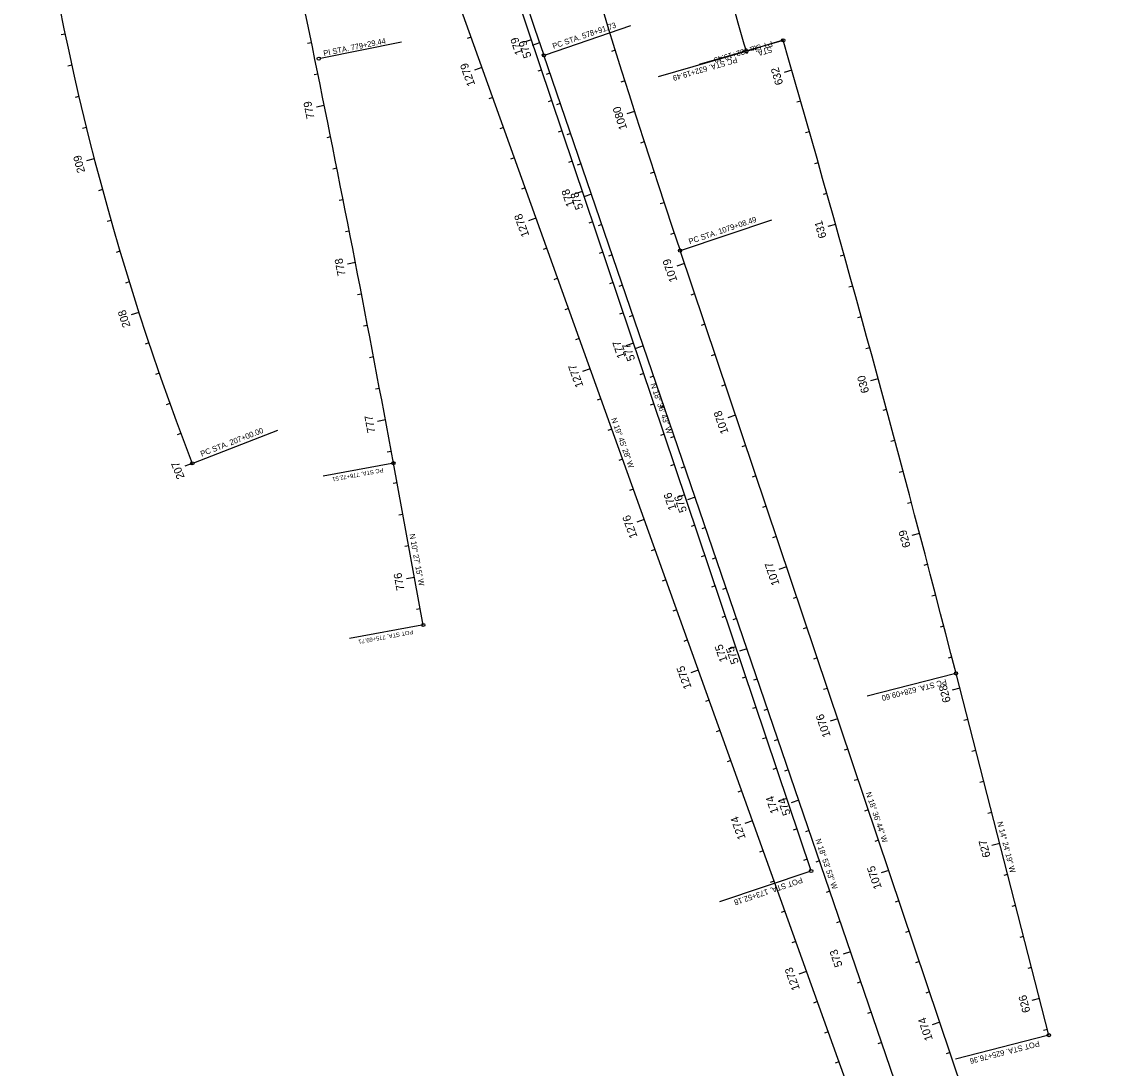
# Model space of a CAD drawing. Extents: x 919452 to 931278, y 583254 to 665650.
# Drawn here: x 928968 to 929643, y 633142 to 633795 of the extents above; entities that cross this region are included whole.
import ezdxf

# ---------------------------------------------------------------- set-up
doc = ezdxf.new("R2010")
doc.units = 0
for name, color, linetype in [('CLConst_dp', 7, 'Continuous'), ('CurveDataLabel_dp', 7, 'Continuous'), ('StationTicL_dp', 7, 'Continuous'), ('StationTicS_dp', 7, 'Continuous'), ('TextBLStation', 7, 'Continuous'), ('TextLabel', 7, 'Continuous')]:
    doc.layers.add(name, color=color, linetype=linetype)

msp = doc.modelspace()

# ---------------------------------------------------------------- linework, layer by layer
at = {"layer": 'CLConst_dp'}
for p, q in [((929494.71, 633100.38), (929187.7, 633955.08)), ((929461.08, 633264.99), (929269.59, 633833.59)), ((929443.57, 633783.76), (929420.55, 633776.95)), ((929642.97, 632755.12), (929294.03, 633774.41)), ((929620.57, 632935.53), (929379.13, 633652.46)), ((929218.69, 633418.59), (929200.03, 633519.68)), ((929609.57, 633162.46), (929551.54, 633388.36))]:
    msp.add_line(p, q, dxfattribs=at)
for centre, radius, start, end in [((934714.76, 635630.15), 5729.58, 175.955434, 198.89818), ((934799.58, 635477.92), 5719.58, 193.88471, 198.61214), ((915974, 631079.31), 13449.29, 10.454203, 12.643022), ((930687.21, 634143.64), 1729.38, 186.13885, 201.15388), ((916462.13, 630026.27), 13490.3, 16.142538, 16.766064), ((916462.13, 630026.27), 13514.3, 14.405367, 16.143157)]:
    msp.add_arc(centre, radius, start, end, dxfattribs=at)
at = {"layer": 'CurveDataLabel_dp'}
for p, q in [((929294.97, 633774.74), (929348.29, 633792.99)), ((929442.61, 633783.48), (929391.12, 633768.58)), ((929442.61, 633783.48), (929420.3, 633777.02)), ((929154.39, 633772.54), (929205.04, 633782.89)), ((929419.59, 633776.67), (929365.54, 633761.02)), ((929422.09, 633777.4), (929429.64, 633779.64)), ((929380.08, 633652.78), (929436.38, 633671.74)), ((929075.29, 633519.91), (929127.76, 633540.22)), ((929199.05, 633519.5), (929156.24, 633511.6)), ((929217.7, 633418.41), (929172.61, 633410.09)), ((929550.57, 633388.11), (929496.08, 633374.12)), ((929460.13, 633264.67), (929403.82, 633245.7)), ((929608.6, 633162.21), (929551.1, 633147.44))]:
    msp.add_line(p, q, dxfattribs=at)
for centre in [(929443.57, 633783.76), (929443.57, 633783.76), (929420.55, 633776.95), (929153.41, 633772.34), (929294.03, 633774.41), (929379.13, 633652.46), (929074.36, 633519.55), (929200.03, 633519.68), (929218.69, 633418.59), (929551.54, 633388.36), (929461.08, 633264.99), (929609.57, 633162.46)]:
    msp.add_circle(centre, 1, dxfattribs=at)
at = {"layer": 'StationTicL_dp'}
for p, q in [((929286.24, 633784.16), (929281.5, 633782.56)), ((929291.35, 633782.24), (929286.62, 633780.62)), ((929255.3, 633766.88), (929250.6, 633765.19)), ((929448.97, 633765.04), (929444.17, 633763.65)), ((929156.86, 633743.04), (929151.96, 633742.05)), ((929350.62, 633739.41), (929345.85, 633737.89)), ((929013.12, 633709.83), (929008.28, 633708.57)), ((929318.16, 633689.39), (929313.42, 633687.79)), ((929323.74, 633687.63), (929319.01, 633686.01)), ((929289.11, 633672.77), (929284.4, 633671.08)), ((929476.28, 633668.84), (929471.47, 633667.49)), ((929176.31, 633644.94), (929171.4, 633643.99)), ((929381.84, 633644.41), (929377.1, 633642.82)), ((929040.99, 633613.8), (929036.23, 633612.27)), ((929350.07, 633594.62), (929345.33, 633593.02)), ((929356.13, 633593.02), (929351.4, 633591.4)), ((929322.91, 633578.66), (929318.21, 633576.97)), ((929502.88, 633572.44), (929498.05, 633571.13)), ((929413.75, 633549.64), (929409.02, 633548.05)), ((929195.02, 633546.71), (929190.1, 633545.79)), ((929074.36, 633519.55), (929069.7, 633517.75)), ((929381.99, 633499.85), (929377.25, 633498.25)), ((929388.52, 633498.41), (929383.78, 633496.79)), ((929356.72, 633484.54), (929352.01, 633482.85)), ((929528.76, 633475.85), (929523.93, 633474.57)), ((929445.67, 633454.87), (929440.93, 633453.28)), ((929213.19, 633448.38), (929208.27, 633447.47)), ((929413.9, 633405.08), (929409.16, 633403.48)), ((929420.9, 633403.8), (929416.17, 633402.18)), ((929390.52, 633390.43), (929385.81, 633388.74)), ((929553.93, 633379.07), (929549.09, 633377.82)), ((929477.59, 633360.1), (929472.85, 633358.51)), ((929445.82, 633310.31), (929441.08, 633308.71)), ((929453.29, 633309.19), (929448.56, 633307.57)), ((929424.32, 633296.32), (929419.62, 633294.63)), ((929578.81, 633282.21), (929573.97, 633280.97)), ((929509.5, 633265.33), (929504.76, 633263.74)), ((929485.68, 633214.58), (929480.95, 633212.96)), ((929458.13, 633202.2), (929453.42, 633200.51)), ((929603.69, 633185.36), (929598.84, 633184.11)), ((929541.42, 633170.56), (929536.68, 633168.97))]:
    msp.add_line(p, q, dxfattribs=at)
at = {"layer": 'StationTicS_dp'}
for p, q in [((928994.85, 633787.71), (928992.4, 633787.19)), ((929248.54, 633785.7), (929246.19, 633784.86)), ((929148.88, 633782.23), (929146.43, 633781.73)), ((929338.59, 633777.56), (929336.21, 633776.82)), ((929420.41, 633777.44), (929418.01, 633776.74)), ((928999.08, 633768.16), (928996.64, 633767.62)), ((929292.62, 633765.2), (929290.25, 633764.41)), ((929297.83, 633763.31), (929295.46, 633762.5)), ((929152.89, 633762.64), (929150.44, 633762.14)), ((929344.57, 633758.48), (929342.19, 633757.72)), ((929003.53, 633748.66), (929001.1, 633748.09)), ((929262.06, 633748.06), (929259.71, 633747.21)), ((929299.01, 633746.25), (929296.64, 633745.45)), ((929304.3, 633744.39), (929301.94, 633743.58)), ((929454.49, 633745.81), (929452.09, 633745.12)), ((929008.22, 633729.22), (929005.79, 633728.62)), ((929160.81, 633723.43), (929158.36, 633722.94)), ((929268.82, 633729.24), (929266.47, 633728.39)), ((929305.39, 633727.3), (929303.02, 633726.5)), ((929310.78, 633725.47), (929308.42, 633724.66)), ((929459.98, 633726.58), (929457.58, 633725.9)), ((929356.73, 633720.37), (929354.35, 633719.6)), ((929275.58, 633710.41), (929273.23, 633709.57)), ((929164.73, 633703.82), (929162.28, 633703.33)), ((929311.77, 633708.34), (929309.4, 633707.54)), ((929317.26, 633706.55), (929314.89, 633705.74)), ((929465.44, 633707.34), (929463.04, 633706.66)), ((929362.91, 633701.35), (929360.53, 633700.57)), ((929018.25, 633690.5), (929015.84, 633689.84)), ((929282.35, 633691.59), (929279.99, 633690.75)), ((929168.62, 633684.2), (929166.16, 633683.71)), ((929369.15, 633682.35), (929366.78, 633681.56)), ((929470.88, 633688.09), (929468.47, 633687.42)), ((929023.6, 633671.23), (929021.2, 633670.54)), ((929324.54, 633670.43), (929322.17, 633669.64)), ((929330.22, 633668.7), (929327.85, 633667.89)), ((929172.48, 633664.57), (929170.02, 633664.09)), ((929375.47, 633663.37), (929373.09, 633662.58)), ((929029.18, 633652.02), (929026.78, 633651.31)), ((929295.87, 633653.95), (929293.51, 633653.1)), ((929330.92, 633651.48), (929328.55, 633650.68)), ((929336.69, 633649.78), (929334.33, 633648.97)), ((929481.66, 633649.57), (929479.25, 633648.9)), ((929302.63, 633635.12), (929300.28, 633634.28)), ((929034.97, 633632.88), (929032.58, 633632.14)), ((929337.3, 633632.53), (929334.94, 633631.73)), ((929343.17, 633630.86), (929340.81, 633630.05)), ((929487, 633630.3), (929484.6, 633629.64)), ((929180.11, 633625.31), (929177.65, 633624.83)), ((929388.22, 633625.46), (929385.85, 633624.66)), ((929309.39, 633616.3), (929307.04, 633615.46)), ((929343.69, 633613.57), (929341.32, 633612.77)), ((929349.65, 633611.94), (929347.28, 633611.13)), ((929492.32, 633611.02), (929489.91, 633610.36)), ((929183.88, 633605.67), (929181.42, 633605.2)), ((929394.6, 633606.5), (929392.24, 633605.71)), ((929047.23, 633594.8), (929044.86, 633594.01)), ((929316.15, 633597.48), (929313.8, 633596.63)), ((929400.99, 633587.55), (929398.62, 633586.75)), ((929497.61, 633591.74), (929495.2, 633591.08)), ((929187.62, 633586.02), (929185.16, 633585.55)), ((929053.68, 633575.87), (929051.32, 633575.05)), ((929356.45, 633575.66), (929354.08, 633574.87)), ((929362.6, 633574.09), (929360.24, 633573.28)), ((929407.37, 633568.6), (929405, 633567.8)), ((929191.33, 633566.37), (929188.88, 633565.91)), ((929060.36, 633557.02), (929058.01, 633556.17)), ((929329.67, 633559.83), (929327.32, 633558.99)), ((929362.84, 633556.71), (929360.47, 633555.91)), ((929369.08, 633555.17), (929366.72, 633554.36)), ((929508.11, 633553.14), (929505.7, 633552.48)), ((929336.43, 633541.01), (929334.08, 633540.17)), ((929067.25, 633538.25), (929064.91, 633537.37)), ((929369.22, 633537.76), (929366.85, 633536.96)), ((929375.56, 633536.25), (929373.19, 633535.44)), ((929513.32, 633533.83), (929510.9, 633533.18)), ((929198.67, 633527.05), (929196.21, 633526.59)), ((929420.14, 633530.69), (929417.77, 633529.89)), ((929343.19, 633522.19), (929340.84, 633521.34)), ((929375.6, 633518.8), (929373.23, 633518)), ((929382.04, 633517.33), (929379.67, 633516.52)), ((929518.49, 633514.51), (929516.08, 633513.86)), ((929202.3, 633507.38), (929199.84, 633506.93)), ((929426.52, 633511.73), (929424.15, 633510.94)), ((929349.95, 633503.37), (929347.6, 633502.52)), ((929523.64, 633495.18), (929521.22, 633494.54)), ((929205.93, 633487.71), (929203.47, 633487.26)), ((929432.9, 633492.78), (929430.53, 633491.98)), ((929388.37, 633480.89), (929386, 633480.1)), ((929394.99, 633479.48), (929392.63, 633478.67)), ((929439.29, 633473.83), (929436.92, 633473.03)), ((929209.56, 633468.04), (929207.1, 633467.59)), ((929363.48, 633465.72), (929361.12, 633464.88)), ((929394.75, 633461.94), (929392.38, 633461.14)), ((929401.47, 633460.56), (929399.11, 633459.75)), ((929533.85, 633456.51), (929531.43, 633455.87)), ((929370.24, 633446.9), (929367.88, 633446.05)), ((929401.14, 633442.98), (929398.77, 633442.19)), ((929407.95, 633441.64), (929405.58, 633440.83)), ((929452.05, 633435.92), (929449.68, 633435.12)), ((929538.91, 633437.16), (929536.49, 633436.53)), ((929216.82, 633428.71), (929214.36, 633428.25)), ((929377, 633428.08), (929374.65, 633427.23)), ((929407.52, 633424.03), (929405.15, 633423.23)), ((929414.43, 633422.72), (929412.06, 633421.91)), ((929458.44, 633416.96), (929456.07, 633416.17)), ((929543.95, 633417.8), (929541.53, 633417.17)), ((929383.76, 633409.25), (929381.41, 633408.41)), ((929548.95, 633398.44), (929546.53, 633397.81)), ((929464.82, 633398.01), (929462.45, 633397.21)), ((929420.28, 633386.12), (929417.92, 633385.32)), ((929427.38, 633384.88), (929425.02, 633384.07)), ((929471.2, 633379.06), (929468.83, 633378.26)), ((929397.28, 633371.61), (929394.93, 633370.76)), ((929426.67, 633367.17), (929424.3, 633366.37)), ((929433.86, 633365.95), (929431.49, 633365.14)), ((929558.91, 633359.7), (929556.49, 633359.07)), ((929404.04, 633352.78), (929401.69, 633351.94)), ((929433.05, 633348.21), (929430.68, 633347.42)), ((929440.34, 633347.03), (929437.97, 633346.22)), ((929483.97, 633341.15), (929481.6, 633340.35)), ((929563.88, 633340.33), (929561.46, 633339.7)), ((929410.8, 633333.96), (929408.45, 633333.12)), ((929439.43, 633329.26), (929437.06, 633328.46)), ((929446.82, 633328.11), (929444.45, 633327.3)), ((929490.35, 633322.19), (929487.98, 633321.4)), ((929568.86, 633320.95), (929566.44, 633320.33)), ((929417.56, 633315.14), (929415.21, 633314.29)), ((929496.74, 633303.24), (929494.37, 633302.44)), ((929573.83, 633301.58), (929571.41, 633300.96)), ((929452.2, 633291.35), (929449.83, 633290.55)), ((929459.77, 633290.27), (929457.41, 633289.46)), ((929503.12, 633284.29), (929500.75, 633283.49)), ((929431.09, 633277.49), (929428.73, 633276.65)), ((929458.58, 633272.4), (929456.21, 633271.6)), ((929466.25, 633271.34), (929463.88, 633270.53)), ((929437.85, 633258.67), (929435.49, 633257.83)), ((929583.78, 633262.84), (929581.36, 633262.22)), ((929472.73, 633252.42), (929470.36, 633251.61)), ((929515.89, 633246.38), (929513.52, 633245.58)), ((929588.76, 633243.47), (929586.34, 633242.85)), ((929444.61, 633239.85), (929442.25, 633239)), ((929479.2, 633233.5), (929476.84, 633232.69)), ((929522.27, 633227.42), (929519.9, 633226.63)), ((929593.74, 633224.1), (929591.31, 633223.48)), ((929451.37, 633221.03), (929449.02, 633220.18)), ((929528.65, 633208.47), (929526.28, 633207.67)), ((929598.71, 633204.73), (929596.29, 633204.11)), ((929492.16, 633195.66), (929489.79, 633194.85)), ((929535.03, 633189.52), (929532.67, 633188.72)), ((929464.89, 633183.38), (929462.54, 633182.54)), ((929498.64, 633176.73), (929496.27, 633175.92)), ((929471.65, 633164.56), (929469.3, 633163.71)), ((929608.66, 633165.98), (929606.24, 633165.36)), ((929505.11, 633157.81), (929502.75, 633157)), ((929547.8, 633151.61), (929545.43, 633150.81)), ((929478.41, 633145.74), (929476.06, 633144.89))]:
    msp.add_line(p, q, dxfattribs=at)

# ---------------------------------------------------------------- texts
at = {"layer": 'CurveDataLabel_dp'}
for s, height, rotation, p in [('PC STA. 578+91.73', 3.5, 18.89818, (929300.08, 633778.34)), ('PI STA. 779+29.44', 3.5, 11.54861, (929156.67, 633773.9)), ('PT Sta 632+19.49', 3.5, 196.14316, (929436.36, 633783.49)), (' STA. ', 3.5, 196.14316, (929437.33, 633780.13)), ('PC STA. 632+19.49', 3.5, 196.14254, (929414.32, 633773.32)), ('PC STA. 1079+08.49', 3.5, 18.61214, (929385.2, 633656.35)), ('PC STA. 207+00.00', 3.5, 21.15388, (929080.26, 633523.71)), ('PC STA. 776+72.51', 2.625, 190.4542, (929193.47, 633516.69)), ('POT STA. 775+69.71', 2.625, 190.4542, (929212.12, 633415.6)), ('PC STA. 628+09.60', 3.5, 194.40537, (929545.2, 633384.93)), ('POT STA. 173+52.18', 3.5, 198.61187, (929455, 633261.09)), ('POT STA. 625+76.36', 3.5, 194.40537, (929603.22, 633159.02))]:
    msp.add_text(s, height=height, rotation=rotation, dxfattribs=at).set_placement(p)
at = {"layer": 'TextBLStation'}
for s, rotation, p in [('179', 108.61187, (929281.22, 633775.57)), ('579', 108.81551, (929286.36, 633773.63)), ('1279', 109.75791, (929251.21, 633756.09)), ('632', 106.06054, (929443.59, 633756.63)), ('779', 101.42334, (929150.81, 633735.15)), ('1080', 107.69545, (929346.14, 633728.78)), ('209', 104.52772, (929007.5, 633701.62)), ('178', 108.61187, (929313.14, 633680.77)), ('578', 108.89818, (929318.77, 633678.98)), ('1278', 109.75791, (929285.03, 633661.94)), ('631', 105.63658, (929470.71, 633660.91)), ('778', 100.99733, (929170.2, 633637.06)), ('1079', 108.61214, (929377.53, 633633.7)), ('208', 107.8408, (929035.86, 633605.25)), ('177', 108.61187, (929345.03, 633586.09)), ('577', 108.89818, (929351.13, 633584.46)), ('1277', 109.75791, (929318.8, 633567.92)), ('630', 105.21261, (929497.35, 633564.18)), ('777', 100.57132, (929188.83, 633538.97)), ('1078', 108.61214, (929409.46, 633538.89)), ('207', 111.15388, (929069.7, 633510.81)), ('176', 108.61187, (929376.96, 633491.26)), ('576', 108.89818, (929383.54, 633489.8)), ('1276', 109.75791, (929352.62, 633473.75)), ('629', 104.78865, (929523.18, 633467.62)), ('1077', 108.61214, (929441.34, 633444.22)), ('776', 100.4542, (929207, 633440.59)), ('175', 108.61187, (929408.89, 633396.46)), ('575', 108.89818, (929415.93, 633395.16)), ('1275', 109.75791, (929386.44, 633379.6)), ('628', 104.40537, (929548.3, 633370.84)), ('1076', 108.61214, (929473.28, 633349.39)), ('174', 108.61187, (929440.78, 633301.76)), ('574', 108.89818, (929448.3, 633300.62)), ('1274', 109.75791, (929420.22, 633285.56)), ('627', 104.40537, (929573.16, 633274.08)), ('1075', 108.61214, (929505.21, 633254.59)), ('573', 108.89818, (929480.72, 633205.91)), ('1273', 109.75791, (929454.06, 633191.35)), ('626', 104.40537, (929598.05, 633177.16)), ('1074', 108.61214, (929537.1, 633159.89))]:
    msp.add_text(s, height=5, rotation=rotation, dxfattribs=at).set_placement(p)
at = {"layer": 'TextLabel'}
for s, rotation, p in [('N 18%%d 36\' 43" W', 288.61187, (929360.55, 633568.99)), ('N 19%%d 45\' 28" W', 289.75791, (929336.02, 633547.33)), ('N 10%%d 27\' 15" W', 280.4542, (929210.01, 633475.27)), ('N 18%%d 36\' 44" W', 288.61214, (929495.06, 633313.69)), ('N 14%%d 24\' 19" W', 284.40537, (929577.23, 633295.41)), ('N 18%%d 53\' 53" W', 288.89818, (929463.61, 633284.44))]:
    msp.add_text(s, height=3.5, rotation=rotation, dxfattribs=at).set_placement(p)

doc.saveas('drawing.dxf')
